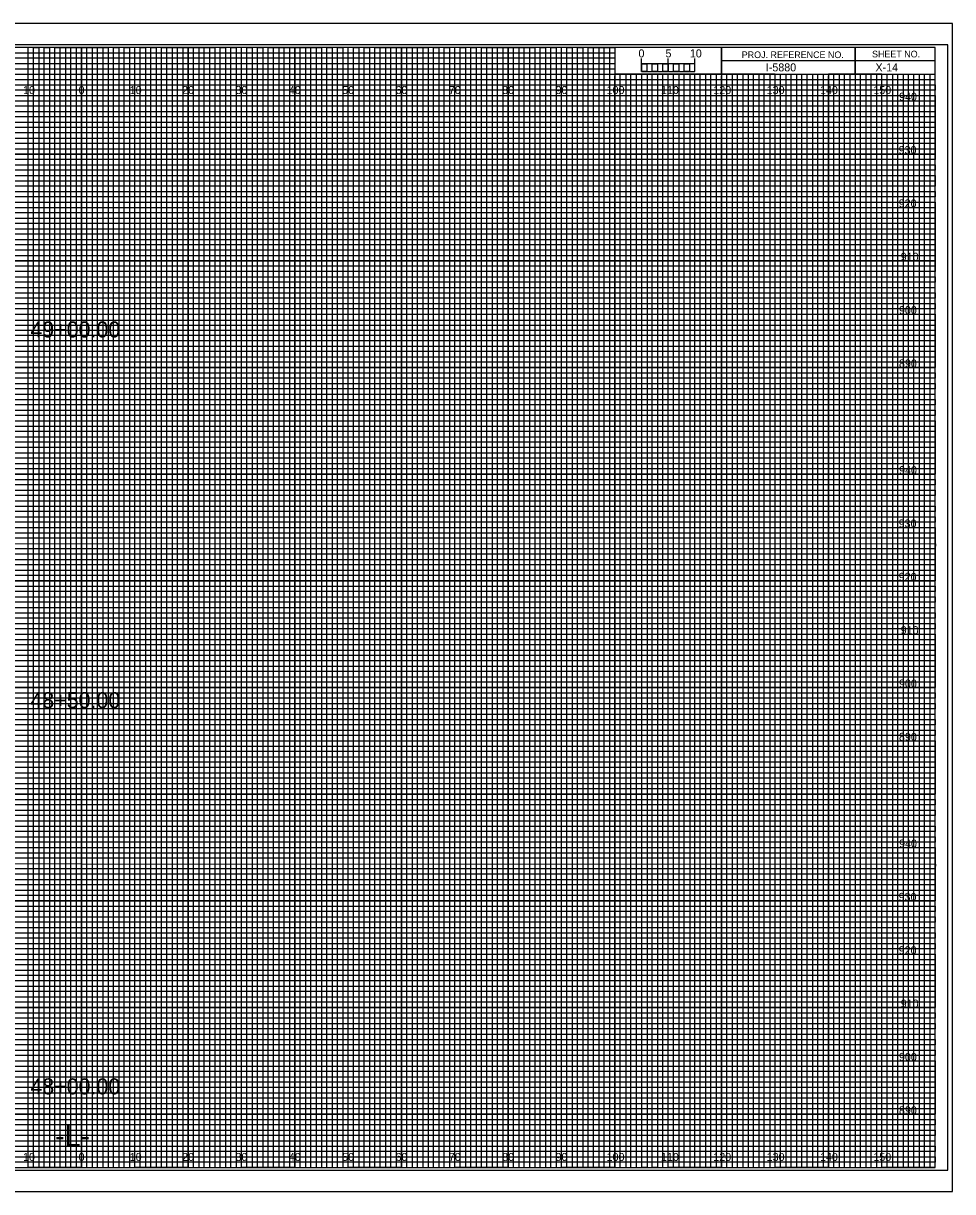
# Model space of a CAD drawing. Extents: x -13 to 323, y -4 to 3074.
# Drawn here: x 149.1 to 323.3, y 2635.5 to 2854.5 of the extents above; entities that cross this region are included whole.
import ezdxf

# ---------------------------------------------------------------- set-up
doc = ezdxf.new("R2010")
doc.units = 0
for name, color, linetype in [('Prop XS Alignment Label', 7, 'Continuous'), ('Prop XS Bar Scale Labels', 7, 'Continuous'), ('Prop XS Elevation Labels', 7, 'Continuous'), ('Prop XS Offset Labels', 7, 'Continuous'), ('Prop XS Project Number', 7, 'Continuous'), ('Prop XS Sheet Number', 7, 'Continuous'), ('Prop XS Station Labels', 7, 'Continuous'), ('Sheet Cross Section CELL', 7, 'Continuous'), ('Sheet Cross Section Grid Major CELL', 7, 'Continuous'), ('Sheet Cross Section Grid Middle CELL', 7, 'Continuous'), ('Sheet Cross Section Grid Minor 1 CELL', 7, 'Continuous'), ('Sheet Cross Section Grid Minor 2 CELL', 7, 'Continuous'), ('Sheet Cross Section Scale CELL', 7, 'Continuous'), ('Sheet Cutting Line CELL', 7, 'Continuous'), ('Sheet DOT Grid CELL', 7, 'Continuous'), ('Sheet Plot Border Inside CELL', 7, 'Continuous'), ('Sheet Plot Border Outside CELL', 7, 'Continuous')]:
    doc.layers.add(name, color=color, linetype=linetype)

msp = doc.modelspace()

# ---------------------------------------------------------------- linework, layer by layer
at = {"layer": 'Sheet Cross Section CELL'}
for p, q in [((305, 2850), (305, 2845)), ((305, 2845), (305, 2850)), ((280, 2847.5), (280, 2845)), ((320, 2847.49), (280, 2847.49)), ((280, 2845), (320, 2845))]:
    msp.add_line(p, q, dxfattribs=at)
for points in [[(320, 2850), (0, 2850), (0, 2640), (320, 2640)], [(280, 2850), (260, 2850), (260, 2845.03), (280, 2845.03)], [(320, 2850), (280, 2850), (280, 2845), (320, 2845)]]:
    msp.add_lwpolyline(points, close=True, dxfattribs=at)
at = {"layer": 'Sheet Cross Section Grid Major CELL'}
for p, q in [((150, 2850), (140, 2850)), ((150, 2640), (150, 2850)), ((170, 2850), (160, 2850)), ((160, 2850), (160, 2640)), ((170, 2640), (170, 2850)), ((190, 2850), (180, 2850)), ((180, 2850), (180, 2640)), ((190, 2640), (190, 2850)), ((210, 2850), (200, 2850)), ((200, 2850), (200, 2640)), ((210, 2640), (210, 2850)), ((230, 2850), (220, 2850)), ((220, 2850), (220, 2640)), ((230, 2640), (230, 2850)), ((250, 2850), (240, 2850)), ((240, 2850), (240, 2640)), ((250, 2640), (250, 2850)), ((260, 2850), (260, 2640)), ((270, 2640), (270, 2845)), ((290, 2845), (280, 2845)), ((280, 2845), (280, 2640)), ((290, 2640), (290, 2845)), ((310, 2845), (300, 2845)), ((300, 2845), (300, 2640)), ((310, 2640), (310, 2845)), ((160, 2640), (150, 2640)), ((180, 2640), (170, 2640)), ((200, 2640), (190, 2640)), ((220, 2640), (210, 2640)), ((240, 2640), (230, 2640)), ((260, 2640), (250, 2640)), ((280, 2640), (270, 2640)), ((300, 2640), (290, 2640)), ((320, 2640), (310, 2640)), ((320, 2640), (320, 2640))]:
    msp.add_line(p, q, dxfattribs=at)
for points in [[(0, 2840), (320, 2840), (320, 2830), (0, 2830)], [(0, 2820), (320, 2820), (320, 2810), (0, 2810)], [(0, 2800), (320, 2800), (320, 2790), (0, 2790)], [(0, 2780), (320, 2780), (320, 2770), (0, 2770)], [(0, 2760), (320, 2760), (320, 2750), (0, 2750)], [(0, 2740), (320, 2740), (320, 2730), (0, 2730)], [(0, 2720), (320, 2720), (320, 2710), (0, 2710)], [(0, 2700), (320, 2700), (320, 2690), (0, 2690)], [(0, 2680), (320, 2680), (320, 2670), (0, 2670)], [(0, 2660), (320, 2660), (320, 2650), (0, 2650)]]:
    msp.add_lwpolyline(points, dxfattribs=at)
at = {"layer": 'Sheet Cross Section Grid Middle CELL'}
for points in [[(145, 2640), (155, 2640), (155, 2850), (165, 2850), (165, 2640), (175, 2640), (175, 2850), (185, 2850), (185, 2640), (195, 2640), (195, 2850), (205, 2850), (205, 2640), (215, 2640), (215, 2850), (225, 2850), (225, 2640), (235, 2640), (235, 2850), (245, 2850), (245, 2640), (255, 2640), (255, 2850), (259.93, 2850), (260, 2850), (260, 2845), (264.99, 2845), (264.99, 2640), (275, 2640), (275, 2845), (285, 2845), (285, 2640), (295, 2640), (295, 2845), (305, 2845), (305, 2640), (315, 2640), (315, 2845)], [(0, 2845), (275, 2845)], [(0, 2825), (320, 2825), (320, 2835), (0, 2835)], [(0, 2805), (320, 2805), (320, 2815), (0, 2815)], [(0, 2785), (320, 2785), (320, 2795), (0, 2795)], [(0, 2765), (320, 2765), (320, 2775), (0, 2775)], [(0, 2745), (320, 2745), (320, 2755), (0, 2755)], [(0, 2725), (320, 2725), (320, 2735), (0, 2735)], [(0, 2705), (320, 2705), (320, 2715), (0, 2715)], [(0, 2685), (320, 2685), (320, 2695), (0, 2695)], [(0, 2665), (320, 2665), (320, 2675), (0, 2675)], [(0, 2645), (320, 2645), (320, 2655), (0, 2655)]]:
    msp.add_lwpolyline(points, dxfattribs=at)
at = {"layer": 'Sheet Cross Section Grid Minor 1 CELL'}
for p, q in [((0, 2849), (260, 2849)), ((260, 2847.98), (0, 2847.98)), ((0, 2847), (260, 2847)), ((260, 2849), (260, 2847.98)), ((260, 2847), (260, 2845.89)), ((260, 2845.89), (0, 2845.89)), ((0, 2844), (320, 2844))]:
    msp.add_line(p, q, dxfattribs=at)
for points in [[(0, 2843), (270, 2843), (320, 2843), (320, 2842), (0, 2842)], [(0, 2841), (320, 2841), (320, 2839), (0, 2839)], [(0, 2838), (320, 2838), (320, 2837), (0, 2836.98)], [(0, 2836), (320, 2836), (320, 2834), (0, 2834)], [(0, 2833), (320, 2833), (320, 2832), (0, 2832)], [(0, 2831), (320, 2831), (320, 2829), (0, 2829)], [(0, 2828), (320, 2828), (320, 2827), (0, 2827)], [(0, 2826), (320, 2826), (320, 2824), (0, 2824)], [(0, 2823), (320, 2823), (320, 2822), (0, 2822)], [(0, 2821), (320, 2821), (320, 2819), (0, 2819)], [(0, 2818), (320, 2818), (320, 2817), (0, 2817)], [(0, 2816), (320, 2816), (320, 2813.95), (320, 2813), (320, 2812), (0, 2812)], [(0, 2814), (320, 2814), (320, 2813), (0, 2813)], [(0, 2811), (320, 2811), (320, 2809), (0, 2809.03)], [(0, 2809.03), (320, 2809), (320, 2808), (0, 2808)], [(0, 2807), (320, 2807), (320, 2806), (0, 2806)], [(0, 2804), (320, 2804), (320, 2803), (0, 2803)], [(0, 2802), (320, 2802), (320, 2801), (0, 2801)], [(-0.07, 2798.89), (320, 2798.89), (320, 2797.88), (-0.07, 2797.88)], [(0, 2797), (320, 2797), (320, 2796), (0, 2796)], [(0, 2794), (320, 2794), (320, 2793), (0, 2793)], [(0, 2792), (320, 2792), (320, 2791), (0, 2791)], [(0, 2789), (320, 2789), (320, 2788), (0, 2788)], [(0, 2787), (320, 2787), (320, 2786), (0, 2786)], [(0, 2784), (320, 2784), (320, 2783), (0, 2783)], [(0, 2782), (320, 2782), (320, 2781), (0, 2781)], [(0, 2779), (320, 2779), (319.99, 2777.98), (0, 2778)], [(0, 2777), (320, 2777), (320, 2776), (0, 2776)], [(0, 2774), (320, 2774), (320, 2773), (0, 2773)], [(0, 2772), (320, 2772), (320, 2771), (0, 2771)], [(0, 2769), (320, 2769), (320, 2768), (0, 2768)], [(0, 2767), (320, 2767), (320, 2766), (0, 2766)], [(0, 2764), (320, 2764), (320, 2763), (0, 2763)], [(0, 2762), (320, 2762), (320, 2761), (0, 2761)], [(0, 2759), (320, 2759), (320, 2758), (0, 2758)], [(0, 2756.99), (320.07, 2756.91), (320, 2756), (0, 2756)], [(0, 2754), (320, 2754), (320, 2753), (0, 2753)], [(0, 2752), (320, 2752), (320, 2751), (0, 2751)], [(0, 2749), (320, 2749), (320, 2748), (0, 2748)], [(0, 2747), (320, 2747), (320, 2746), (0, 2746)], [(0, 2744), (320, 2744), (320, 2743), (0, 2743)], [(0, 2742), (320, 2742), (320, 2741), (0, 2741)], [(0, 2739), (320, 2739), (320, 2738), (0, 2738)], [(0, 2737), (320, 2737), (320, 2736), (0, 2736)], [(0, 2734), (320, 2734), (320, 2733), (0, 2733)], [(0, 2732), (320, 2732), (320, 2731), (0, 2731)], [(0, 2729), (320, 2729), (320, 2728), (0, 2728)], [(0, 2727), (320, 2727), (320, 2726), (0, 2726)], [(0, 2724), (320, 2724), (320, 2723), (0, 2723)], [(0, 2722), (320, 2722), (320, 2721), (0, 2721)], [(0, 2719), (320, 2719), (319.99, 2717.98), (0, 2718)], [(0, 2717), (320, 2717), (320, 2716), (0, 2716)], [(0, 2714), (320, 2714), (320, 2713), (0, 2713)], [(0, 2712), (320, 2712), (320, 2711), (0, 2711)], [(0, 2709), (320, 2709), (320, 2708), (0, 2708)], [(0, 2707), (320, 2707), (320, 2706), (0, 2706)], [(0, 2704), (320, 2704), (320, 2703), (0, 2703)], [(0, 2702), (320, 2702), (320, 2701), (0, 2701)], [(0, 2699), (320, 2699), (320, 2698), (0, 2698)], [(0, 2696.99), (320.07, 2696.91), (320, 2696), (0, 2696)], [(0, 2694), (320, 2694), (320, 2693), (0, 2693)], [(0, 2692), (320, 2692), (320, 2691), (0, 2691)], [(0, 2689), (320, 2689), (320, 2688), (0, 2688)], [(0, 2687), (320, 2687), (320, 2686), (0, 2686)], [(0, 2684), (320, 2684), (320, 2683), (0, 2683)], [(0, 2682), (320, 2682), (320, 2681), (0, 2681)], [(0, 2679), (320, 2679), (320, 2678), (0, 2678)], [(0, 2677), (320, 2677), (320, 2676), (0, 2676)], [(0, 2674), (320, 2674), (320, 2673), (0, 2673)], [(0, 2672), (320, 2672), (320, 2671), (0, 2671)], [(0, 2669), (320, 2669), (320, 2668), (0, 2668)], [(0, 2667), (320, 2667), (320, 2666), (0, 2666)], [(0, 2664), (320, 2664), (320, 2663), (0, 2663)], [(0, 2662), (320, 2662), (320, 2661), (0, 2661)], [(0, 2659), (320, 2659), (320, 2658), (0, 2658)], [(0, 2657), (320, 2657), (320, 2656), (0, 2656)], [(0, 2654), (320, 2654), (320, 2653), (0, 2653)], [(0, 2652), (320, 2652), (320, 2651), (0, 2651)], [(0, 2649), (320, 2649), (320, 2648), (0, 2648)], [(0, 2647), (320, 2647), (320, 2646), (0, 2646)], [(0, 2644), (320, 2644), (320, 2643), (0, 2643)], [(0, 2642), (320, 2642), (320, 2641), (0, 2641)]]:
    msp.add_lwpolyline(points, dxfattribs=at)
at = {"layer": 'Sheet Cross Section Grid Minor 2 CELL'}
for p, q in [((267, 2845), (266.01, 2845)), ((266.01, 2845), (266.01, 2640)), ((267, 2640), (267, 2845)), ((269, 2845), (268, 2845)), ((268, 2845), (268, 2640)), ((269, 2640), (269, 2845)), ((266.01, 2640), (265, 2640)), ((268, 2640), (267, 2640))]:
    msp.add_line(p, q, dxfattribs=at)
for points in [[(150, 2640), (151, 2640), (151, 2850), (152, 2850), (152, 2640)], [(152, 2640), (153, 2640), (153, 2850), (154, 2850), (154, 2640)], [(155, 2640), (156, 2640), (156, 2850), (157, 2850), (157, 2640)], [(157, 2640), (158, 2640), (158, 2850), (159, 2850), (159, 2640)], [(160, 2640), (161, 2640), (161, 2850), (162, 2850), (162, 2640)], [(162, 2640), (163, 2640), (163, 2850), (164, 2850), (164, 2640)], [(165, 2640), (166, 2640), (166, 2850), (167, 2850), (167, 2640)], [(167, 2640), (168, 2640), (168, 2850), (169, 2850), (169, 2640)], [(170, 2640), (171, 2640), (171, 2850), (172, 2850), (172, 2640)], [(172, 2640), (173, 2640), (173, 2850), (174, 2850), (174, 2640)], [(175, 2640), (176, 2640), (176, 2850), (177, 2850), (177, 2640)], [(177, 2640), (178, 2640), (178, 2850), (179, 2850), (179, 2640)], [(180, 2640), (181, 2640), (181, 2850), (182, 2850), (182, 2640)], [(182, 2640), (183, 2640), (183, 2850), (184, 2850), (184, 2640)], [(185, 2640), (186, 2640), (186, 2850), (187, 2850), (187, 2640)], [(187, 2640), (188, 2640), (188, 2850), (189, 2850), (189, 2640)], [(190, 2640), (191, 2640), (191, 2850), (192, 2850), (192, 2640)], [(192, 2640), (193, 2640), (193, 2850), (194, 2850), (194, 2640)], [(195, 2640), (196, 2640), (196, 2850), (197, 2850), (197, 2640)], [(197, 2640), (198, 2640), (198, 2850), (199, 2850), (199, 2640)], [(200, 2640), (201, 2640), (201, 2850), (202, 2850), (202, 2640)], [(202, 2640), (203, 2640), (203, 2850), (204, 2850), (204, 2640)], [(205, 2640), (206, 2640), (206, 2850), (207, 2850), (207, 2640)], [(207, 2640), (208, 2640), (208, 2850), (209, 2850), (209, 2640)], [(210, 2640), (211, 2640), (211, 2850), (212, 2850), (212, 2640)], [(212, 2640), (213, 2640), (213, 2850), (214, 2850), (214, 2640)], [(215, 2640), (216, 2640), (216, 2850), (217, 2850), (217, 2640)], [(217, 2640), (218, 2640), (218, 2850), (219, 2850), (219, 2640)], [(220, 2640), (221, 2640), (221, 2850), (222, 2850), (222, 2640)], [(222, 2640), (223, 2640), (223, 2850), (224, 2850), (224, 2640)], [(225, 2640), (226, 2640), (226, 2850), (227, 2850), (227, 2640)], [(227, 2640), (228, 2640), (228, 2850), (229, 2850), (229, 2640)], [(230, 2640), (231, 2640), (231, 2850), (232, 2850), (232, 2640)], [(232, 2640), (233, 2640), (233, 2850), (234, 2850), (234, 2640)], [(235, 2640), (236, 2640), (236, 2850), (237, 2850), (237, 2640)], [(237, 2640), (238, 2640), (238, 2850), (239, 2850), (239, 2640)], [(240, 2640), (241, 2640), (241, 2850), (242, 2850), (242, 2640)], [(242, 2640), (243, 2640), (243, 2850), (244, 2850), (244, 2640)], [(245, 2640), (246, 2640), (246, 2850), (247, 2850), (247, 2640)], [(247, 2640), (248, 2640), (248, 2850), (249, 2850), (249, 2640)], [(250, 2640), (251, 2640), (251, 2850), (252, 2850), (252, 2640)], [(252, 2640), (253, 2640), (253, 2850), (254, 2850), (254, 2640)], [(255, 2640), (256, 2640), (256, 2850), (257, 2850), (257, 2640)], [(257, 2640), (258, 2640), (258, 2850), (259, 2850), (259, 2640)], [(260, 2640), (261, 2640), (261, 2845), (262.02, 2845), (262.02, 2640)], [(262, 2640), (263, 2640), (263, 2845), (263.99, 2845), (263.99, 2640)], [(270, 2640), (270.98, 2640), (270.98, 2845), (272, 2845), (272, 2640)], [(272, 2640), (273, 2640), (273, 2845), (274.05, 2845), (274.05, 2640)], [(275, 2640), (276, 2640), (276, 2845), (277, 2845), (277, 2640)], [(277, 2640), (278, 2640), (278, 2845), (279, 2845), (279, 2640)], [(280, 2640), (281, 2640), (281, 2845), (282, 2845), (282, 2640)], [(282, 2640), (283, 2640), (283, 2845), (284, 2845), (284, 2640)], [(285, 2640), (286, 2640), (286, 2845), (287, 2845), (287, 2640)], [(287, 2640), (288, 2640), (288, 2845), (289, 2845), (289, 2640)], [(290, 2640), (291, 2640), (291, 2845), (292, 2845), (292, 2640)], [(292, 2640), (293, 2640), (293, 2845), (294, 2845), (294, 2640)], [(295, 2640), (296, 2640), (296, 2845), (297, 2845), (297, 2640)], [(297, 2640), (298, 2640), (298, 2845), (299, 2845), (299, 2640)], [(300, 2640), (301, 2640), (301, 2845), (302, 2845), (302, 2640)], [(302, 2640), (303, 2640), (303, 2845), (304, 2845), (304, 2640)], [(305, 2640), (306, 2640), (306, 2845), (307, 2845), (307, 2640)], [(307, 2640), (308, 2640), (308, 2845), (309, 2845), (309, 2640)], [(310, 2640), (311, 2640), (311, 2845), (312, 2845), (312, 2640)], [(312, 2640), (313, 2640), (313, 2845), (314, 2845), (314, 2640)], [(315, 2640), (316, 2640), (316, 2845), (317, 2845), (317, 2640)], [(317, 2640), (318, 2640), (318, 2845), (319, 2845), (319, 2640)]]:
    msp.add_lwpolyline(points, dxfattribs=at)
at = {"layer": 'Sheet Cross Section Scale CELL'}
for p, q in [((265, 2845.49), (265, 2847.9)), ((265, 2846.9), (265, 2847.9)), ((270, 2845.49), (270, 2847.9)), ((275, 2845.49), (275, 2847.9)), ((275, 2846.9), (275, 2847.9))]:
    msp.add_line(p, q, dxfattribs=at)
for points in [[(275, 2846.9), (265, 2846.9), (265, 2845.49), (275, 2845.49)], [(265, 2846.9), (266, 2846.9), (266, 2845.49), (265, 2845.49)], [(267, 2846.9), (268, 2846.9), (268, 2845.49), (267, 2845.49)], [(269, 2846.9), (270, 2846.9), (270, 2845.49), (269, 2845.49)], [(271, 2846.9), (272, 2846.9), (272, 2845.49), (271, 2845.49)], [(273, 2846.9), (274, 2846.9), (274, 2845.49), (273, 2845.49)]]:
    msp.add_lwpolyline(points, close=True, dxfattribs=at)
at = {"layer": 'Sheet Cutting Line CELL'}
for p, q in [((323.3, 2854.5), (-13.4, 2854.5)), ((-13.4, 2635.5), (323.3, 2635.5))]:
    msp.add_line(p, q, dxfattribs=at)
at = {"layer": 'Sheet DOT Grid CELL'}
for p, q in [((150, 2640), (150, 2850)), ((160, 2640), (160, 2850)), ((170, 2640), (170, 2850)), ((180, 2640), (180, 2850)), ((190, 2640), (190, 2850)), ((200, 2640), (200, 2850)), ((210, 2640), (210, 2850)), ((220, 2640), (220, 2850)), ((230, 2640), (230, 2850)), ((240, 2640), (240, 2850)), ((250, 2640), (250, 2850)), ((260, 2640), (260, 2844.69)), ((270, 2640), (270, 2844.69)), ((280, 2640), (280, 2844.69)), ((290, 2640), (290, 2844.69)), ((300, 2640), (300, 2844.69)), ((310, 2640), (310, 2844.69)), ((0, 2840), (320, 2840)), ((0, 2830), (320, 2830)), ((0, 2820), (320, 2820)), ((0, 2810), (320, 2810)), ((0, 2800), (320, 2800)), ((0, 2790), (320, 2790)), ((0, 2780), (320, 2780)), ((0, 2770), (320, 2770)), ((0, 2760), (320, 2760)), ((0, 2750), (320, 2750)), ((0, 2740), (320, 2740)), ((0, 2730), (320, 2730)), ((0, 2720), (320, 2720)), ((0, 2710), (320, 2710)), ((0, 2700), (320, 2700)), ((0, 2690), (320, 2690)), ((0, 2680), (320, 2680)), ((0, 2670), (320, 2670)), ((0, 2660), (320, 2660)), ((0, 2650), (320, 2650))]:
    msp.add_line(p, q, dxfattribs=at)
at = {"layer": 'Sheet Plot Border Inside CELL'}
msp.add_lwpolyline([(-10.8, 2639.5), (322.4, 2639.5), (322.4, 2850.5), (-10.8, 2850.5)], close=True, dxfattribs=at)
at = {"layer": 'Sheet Plot Border Outside CELL'}
msp.add_lwpolyline([(-13.4, 2635.5), (323.3, 2635.5), (323.3, 2854.5), (-13.4, 2854.5)], close=True, dxfattribs=at)

# ---------------------------------------------------------------- texts
at = {"layer": 'Prop XS Alignment Label'}
msp.add_text('-L-', height=4, dxfattribs=at).set_placement((155.06, 2644))
at = {"layer": 'Prop XS Bar Scale Labels'}
for s, p in [('5', (269.47, 2848.12)), ('10', (274.04, 2848.12))]:
    msp.add_text(s, height=1.5, dxfattribs=at).set_placement(p)
at = {"layer": 'Prop XS Elevation Labels'}
for s, p in [('940', (313.26, 2840)), ('930', (313.18, 2830)), ('920', (313.19, 2820)), ('910', (313.57, 2810)), ('900', (313.24, 2800)), ('890', (313.24, 2790)), ('940', (313.26, 2770)), ('930', (313.18, 2760)), ('920', (313.19, 2750)), ('910', (313.57, 2740)), ('900', (313.24, 2730)), ('890', (313.24, 2720)), ('940', (313.26, 2700)), ('930', (313.18, 2690)), ('920', (313.19, 2680)), ('910', (313.57, 2670)), ('900', (313.24, 2660)), ('890', (313.24, 2650))]:
    msp.add_text(s, height=1.5, dxfattribs=at).set_placement(p)
at = {"layer": 'Prop XS Offset Labels'}
for s, p in [('10', (149.04, 2841.25)), ('0', (159.45, 2841.25)), ('0', (159.45, 2841.25)), ('10', (169.04, 2841.25)), ('20', (178.86, 2841.25)), ('30', (188.86, 2841.25)), ('40', (198.86, 2841.25)), ('50', (208.86, 2841.25)), ('60', (218.86, 2841.25)), ('70', (228.86, 2841.25)), ('80', (238.86, 2841.25)), ('90', (248.86, 2841.25)), ('100', (258.44, 2841.25)), ('110', (268.62, 2841.25)), ('120', (278.44, 2841.25)), ('130', (288.44, 2841.25)), ('140', (298.44, 2841.25)), ('150', (308.44, 2841.25)), ('10', (149.04, 2641.25)), ('0', (159.45, 2641.25)), ('0', (159.45, 2641.25)), ('10', (169.04, 2641.25)), ('20', (178.86, 2641.25)), ('30', (188.86, 2641.25)), ('40', (198.86, 2641.25)), ('50', (208.86, 2641.25)), ('60', (218.86, 2641.25)), ('70', (228.86, 2641.25)), ('80', (238.86, 2641.25)), ('90', (248.86, 2641.25)), ('100', (258.44, 2641.25)), ('110', (268.62, 2641.25)), ('120', (278.44, 2641.25)), ('130', (288.44, 2641.25)), ('140', (298.44, 2641.25)), ('150', (308.44, 2641.25))]:
    msp.add_text(s, height=1.5, dxfattribs=at).set_placement(p)
at = {"layer": 'Prop XS Project Number'}
msp.add_text('I-5880', height=1.5, dxfattribs=at).set_placement((288.28, 2845.5))
at = {"layer": 'Prop XS Sheet Number'}
msp.add_text('X-14', height=1.5, dxfattribs=at).set_placement((308.83, 2845.5))
at = {"layer": 'Prop XS Station Labels'}
for s, p in [('49+00.00', (150.41, 2795.62)), ('48+50.00', (150.41, 2726.13)), ('48+00.00', (150.41, 2653.73))]:
    msp.add_text(s, height=3, dxfattribs=at).set_placement(p)
at = {"layer": 'Sheet Cross Section CELL'}
for s, p in [('PROJ. REFERENCE NO.', (283.77, 2847.99)), ('SHEET NO.', (308.19, 2848.12))]:
    msp.add_text(s, height=1.25, dxfattribs=at).set_placement(p)
at = {"layer": 'Sheet Cross Section Scale CELL'}
msp.add_text('0', height=1.5, dxfattribs=at).set_placement((264.41, 2848.12))

doc.saveas('drawing.dxf')
